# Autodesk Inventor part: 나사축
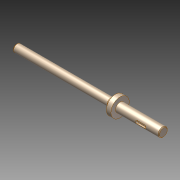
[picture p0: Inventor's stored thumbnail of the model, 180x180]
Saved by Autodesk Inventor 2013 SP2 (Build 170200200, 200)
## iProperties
Created: 2024-07
Part Number: 나사축
Material: Generic
Document SubType Name: Modeling
Designer: 601
Density: 1 g/cm^3
Author: 601
변환 표준: STEP AP214IS
전처리기: Build: 200, Release: 2013 SP2 Update 6 - Date: Thu 07/17/2014
전송 단위: 밀리미터
불확실성: 0.01
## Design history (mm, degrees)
node "나사축1"
node "솔리드1"
node "기준1"
